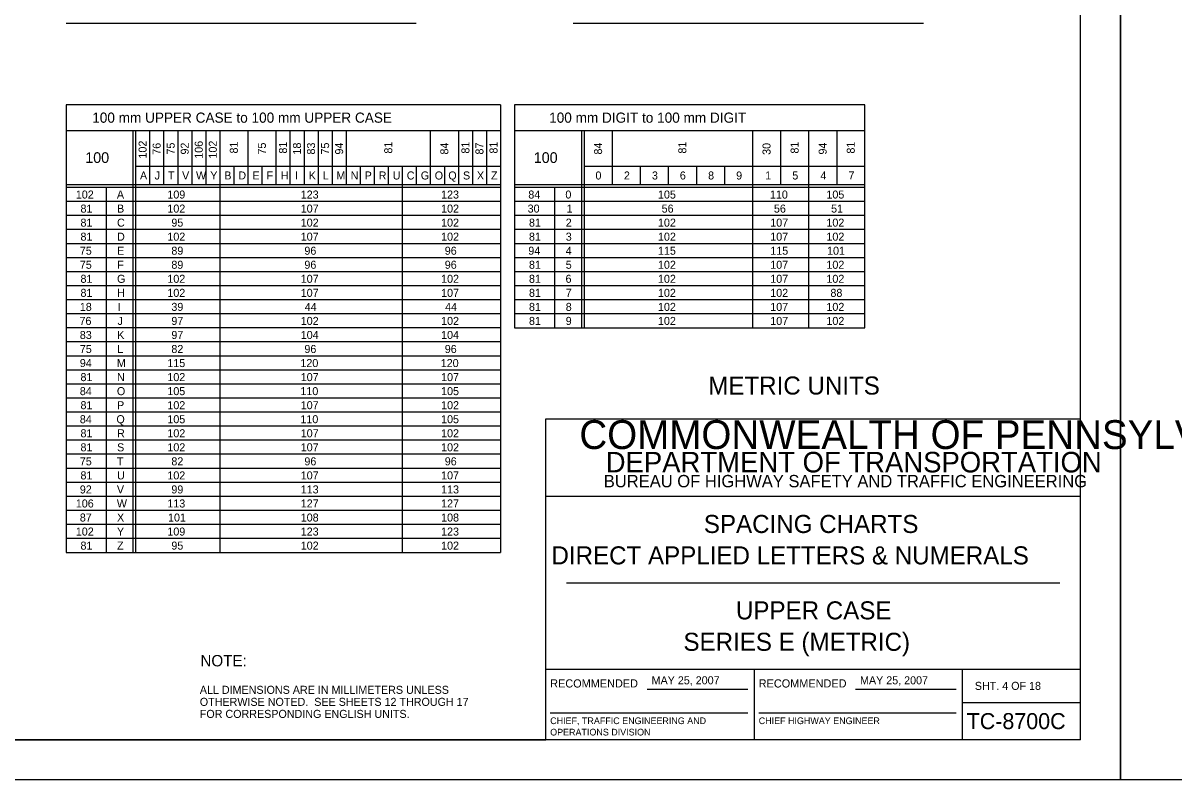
# Model space of a CAD drawing. Extents: x 637580 to 641849, y 297270 to 299646.
# Drawn here: x 638010.8 to 638441.3, y 297269.6 to 297552.6 of the extents above; entities that cross this region are included whole.
import ezdxf

# ---------------------------------------------------------------- set-up
doc = ezdxf.new("R2010")
doc.units = 0
for name, color, linetype in [('1', 7, 'Continuous'), ('2', 7, 'Continuous'), ('XCS-GRID-HVGL', 7, 'Continuous')]:
    doc.layers.add(name, color=color, linetype=linetype)

msp = doc.modelspace()

# ---------------------------------------------------------------- linework, layer by layer
at = {"layer": '1'}
for p, q in [((638406.31, 297284.63), (638406.31, 297848.63)), ((638206.31, 297284.63), (638206.31, 297404.63)), ((638206.31, 297404.63), (638406.31, 297404.63)), ((638406.31, 297375.63), (638206.31, 297375.63)), ((638214.06, 297343.31), (638398.56, 297343.31)), ((638206.31, 297311), (638406.31, 297311)), ((638284.31, 297311), (638284.31, 297284.63)), ((638362.19, 297284.63), (638362.19, 297311)), ((638244.24, 297303.57), (638281.87, 297303.57)), ((638322.24, 297303.57), (638359.87, 297303.57)), ((638362.19, 297298.63), (638406.31, 297298.63)), ((638207.99, 297294.68), (638281.87, 297294.68)), ((638285.99, 297294.68), (638359.87, 297294.68)), ((638406.31, 297284.63), (637620.31, 297284.63)), ((637620.31, 297284.63), (638206.31, 297284.63))]:
    msp.add_line(p, q, dxfattribs=at)
at = {"layer": '2'}
for p, q in [((638026.91, 297552.63), (638157.91, 297552.63)), ((638216.61, 297552.63), (638347.61, 297552.63)), ((638189.41, 297522), (638026.91, 297522)), ((638026.91, 297522), (638026.91, 297354.63)), ((638189.41, 297522), (638189.41, 297354.63)), ((638325.66, 297522), (638194.66, 297522)), ((638194.66, 297522), (638194.66, 297438.63)), ((638325.66, 297438.63), (638325.66, 297522)), ((638026.91, 297512.5), (638189.41, 297512.5)), ((638051.91, 297512.5), (638051.91, 297354.63)), ((638052.91, 297512.5), (638052.91, 297354.63)), ((638058.16, 297512.5), (638058.16, 297492.13)), ((638063.41, 297512.5), (638063.41, 297492.13)), ((638068.66, 297512.5), (638068.66, 297492.13)), ((638073.91, 297512.5), (638073.91, 297492.13)), ((638079.16, 297512.5), (638079.16, 297492.13)), ((638084.41, 297512.5), (638084.41, 297354.63)), ((638094.91, 297512.5), (638094.91, 297492.13)), ((638105.41, 297512.5), (638105.41, 297492.13)), ((638110.66, 297512.5), (638110.66, 297492.13)), ((638115.91, 297512.5), (638115.91, 297492.13)), ((638121.16, 297512.5), (638121.16, 297492.13)), ((638126.41, 297512.5), (638126.41, 297492.13)), ((638131.66, 297512.5), (638131.66, 297492.13)), ((638163.16, 297512.5), (638163.16, 297492.13)), ((638173.66, 297512.5), (638173.66, 297492.13)), ((638178.91, 297512.5), (638178.91, 297492.13)), ((638184.16, 297512.5), (638184.16, 297492.13)), ((638194.66, 297512.5), (638325.66, 297512.5)), ((638219.66, 297512.5), (638219.66, 297438.63)), ((638220.66, 297512.5), (638220.66, 297438.63)), ((638231.16, 297512.5), (638231.16, 297492.13)), ((638283.66, 297512.5), (638283.66, 297438.63)), ((638294.16, 297512.5), (638294.16, 297492.13)), ((638304.66, 297512.5), (638304.66, 297438.63)), ((638315.16, 297512.5), (638315.16, 297492.13)), ((638052.91, 297499.13), (638189.41, 297499.13)), ((638089.66, 297499.13), (638089.66, 297492.13)), ((638100.16, 297499.13), (638100.16, 297492.13)), ((638136.91, 297499.13), (638136.91, 297492.13)), ((638142.16, 297499.13), (638142.16, 297492.13)), ((638147.41, 297499.13), (638147.41, 297492.13)), ((638147.41, 297499.13), (638147.41, 297492.13)), ((638152.66, 297499.13), (638152.66, 297354.63)), ((638157.91, 297499.13), (638157.91, 297492.13)), ((638168.41, 297499.13), (638168.41, 297492.13)), ((638220.66, 297499.13), (638325.66, 297499.13)), ((638241.66, 297499.13), (638241.66, 297492.13)), ((638252.16, 297499.13), (638252.16, 297492.13)), ((638262.66, 297499.13), (638262.66, 297492.13)), ((638273.16, 297499.13), (638273.16, 297492.13)), ((638189.41, 297492.13), (638026.91, 297492.13)), ((638189.41, 297491.13), (638026.91, 297491.13)), ((638041.91, 297491.13), (638041.91, 297354.63)), ((638325.66, 297492.13), (638194.66, 297492.13)), ((638325.66, 297491.13), (638194.66, 297491.13)), ((638209.66, 297491.13), (638209.66, 297438.63)), ((638189.41, 297485.88), (638026.91, 297485.88)), ((638325.66, 297485.88), (638194.66, 297485.88)), ((638189.41, 297480.63), (638026.91, 297480.63)), ((638325.66, 297480.63), (638194.66, 297480.63)), ((638189.41, 297475.38), (638026.91, 297475.38)), ((638325.66, 297475.38), (638194.66, 297475.38)), ((638189.41, 297470.13), (638026.91, 297470.13)), ((638325.66, 297470.13), (638194.66, 297470.13)), ((638189.41, 297464.88), (638026.91, 297464.88)), ((638325.66, 297464.88), (638194.66, 297464.88)), ((638189.41, 297459.63), (638026.91, 297459.63)), ((638325.66, 297459.63), (638194.66, 297459.63)), ((638189.41, 297454.38), (638026.91, 297454.38)), ((638325.66, 297454.38), (638194.66, 297454.38)), ((638189.41, 297449.13), (638026.91, 297449.13)), ((638325.66, 297449.13), (638194.66, 297449.13)), ((638189.41, 297443.88), (638026.91, 297443.88)), ((638325.66, 297443.88), (638194.66, 297443.88)), ((638189.41, 297438.63), (638026.91, 297438.63)), ((638194.66, 297438.63), (638325.66, 297438.63)), ((638189.41, 297433.38), (638026.91, 297433.38)), ((638189.41, 297428.13), (638026.91, 297428.13)), ((638189.41, 297422.88), (638026.91, 297422.88)), ((638189.41, 297417.63), (638026.91, 297417.63)), ((638189.41, 297412.38), (638026.91, 297412.38)), ((638189.41, 297407.13), (638026.91, 297407.13)), ((638189.41, 297401.88), (638026.91, 297401.88)), ((638189.41, 297396.63), (638026.91, 297396.63)), ((638189.41, 297391.38), (638026.91, 297391.38)), ((638189.41, 297386.13), (638026.91, 297386.13)), ((638189.41, 297380.88), (638026.91, 297380.88)), ((638189.41, 297375.63), (638026.91, 297375.63)), ((638189.41, 297370.38), (638026.91, 297370.38)), ((638189.41, 297365.13), (638026.91, 297365.13)), ((638189.41, 297359.88), (638026.91, 297359.88)), ((638026.91, 297354.63), (638026.91, 297354.63)), ((638026.91, 297354.63), (638189.41, 297354.63))]:
    msp.add_line(p, q, dxfattribs=at)
at = {"layer": 'XCS-GRID-HVGL'}
for points in [[(637580.31, 297863.63), (638421.31, 297863.63), (638421.31, 297269.63), (637580.31, 297269.63)], [(638421.31, 297863.63), (639262.31, 297863.63), (639262.31, 297269.63), (638421.31, 297269.63)]]:
    msp.add_lwpolyline(points, close=True, dxfattribs=at)

# ---------------------------------------------------------------- texts
at = {"layer": '1'}
for s, height, p in [('COMMONWEALTH OF PENNSYLVANIA', 10.7828, (638218.9, 297393.36)), ('DEPARTMENT OF TRANSPORTATION', 7.6837, (638228.76, 297384.61)), ('BUREAU OF HIGHWAY SAFETY AND TRAFFIC ENGINEERING', 4.6253, (638228.04, 297379.04)), ('SPACING CHARTS', 6.75, (638265.47, 297361.97)), ('DIRECT APPLIED LETTERS & NUMERALS', 6.75, (638208.47, 297350.22)), ('UPPER CASE', 6.75, (638277.47, 297329.66)), ('SERIES E (METRIC)', 6.75, (638257.84, 297317.91)), ('RECOMMENDED', 3.048, (638207.99, 297304.2)), ('RECOMMENDED', 3.048, (638285.99, 297304.2)), ('SHT. 4 OF 18', 3, (638366.82, 297303.31)), ('TC-8700C', 6, (638363.77, 297288.63)), ('CHIEF, TRAFFIC ENGINEERING AND', 2.5, (638207.99, 297290.51)), ('CHIEF HIGHWAY ENGINEER', 2.5, (638285.99, 297290.51)), ('OPERATIONS DIVISION', 2.5, (638207.99, 297286.26))]:
    msp.add_text(s, height=height, dxfattribs=at).set_placement(p)
at = {"layer": '2'}
for s, height, p in [('100 mm UPPER CASE to 100 mm UPPER CASE', 3.8, (638036.7, 297515.35)), ('100 mm DIGIT to 100 mm DIGIT', 3.8, (638207.61, 297515.35)), ('100', 4, (638034.1, 297500.31)), ('100', 4, (638201.85, 297500.31)), ('A', 3, (638054.56, 297494.13)), ('J', 3, (638060.04, 297494.13)), ('T', 3, (638065.04, 297494.13)), ('V', 3, (638070.31, 297494.13)), ('W', 3, (638075.53, 297494.13)), ('Y', 3, (638080.84, 297494.13)), ('B', 3, (638086.1, 297494.13)), ('D', 3, (638091.35, 297494.13)), ('E', 3, (638096.62, 297494.13)), ('F', 3, (638101.92, 297494.13)), ('H', 3, (638107.19, 297494.13)), ('I', 3, (638112.6, 297494.13)), ('K', 3, (638117.69, 297494.13)), ('L', 3, (638122.94, 297494.13)), ('M', 3, (638128.03, 297494.13)), ('N', 3, (638133.35, 297494.13)), ('P', 3, (638138.6, 297494.13)), ('R', 3, (638143.85, 297494.13)), ('U', 3, (638149.09, 297494.13)), ('C', 3, (638154.35, 297494.13)), ('G', 3, (638159.6, 297494.13)), ('O', 3, (638164.81, 297494.13)), ('Q', 3, (638169.88, 297494.13)), ('S', 3, (638175.37, 297494.13)), ('X', 3, (638180.59, 297494.13)), ('Z', 3, (638185.85, 297494.13)), ('0', 3, (638224.93, 297494.13)), ('2', 3, (638235.56, 297494.13)), ('3', 3, (638246.06, 297494.13)), ('6', 3, (638256.48, 297494.13)), ('8', 3, (638267.06, 297494.13)), ('9', 3, (638277.55, 297494.13)), ('1', 3, (638288.4, 297494.13)), ('5', 3, (638298.56, 297494.13)), ('4', 3, (638309.06, 297494.13)), ('7', 3, (638319.56, 297494.13)), ('102', 3, (638030.56, 297487)), ('A', 3, (638045.93, 297487)), ('109', 3, (638064.8, 297487)), ('123', 3, (638114.69, 297487)), ('123', 3, (638167.19, 297487)), ('84', 3, (638199.81, 297487)), ('0', 3, (638213.68, 297487)), ('105', 3, (638248.31, 297487)), ('110', 3, (638290.18, 297487)), ('105', 3, (638311.31, 297487)), ('81', 3, (638032.31, 297481.75)), ('B', 3, (638045.98, 297481.75)), ('102', 3, (638064.8, 297481.75)), ('107', 3, (638114.69, 297481.75)), ('102', 3, (638167.19, 297481.75)), ('30', 3, (638199.56, 297481.75)), ('1', 3, (638214.15, 297481.75)), ('56', 3, (638249.69, 297481.75)), ('56', 3, (638291.68, 297481.75)), ('51', 3, (638313.06, 297481.75)), ('81', 3, (638032.31, 297476.5)), ('C', 3, (638045.98, 297476.5)), ('95', 3, (638066.3, 297476.5)), ('102', 3, (638114.69, 297476.5)), ('102', 3, (638167.19, 297476.5)), ('81', 3, (638200.06, 297476.5)), ('2', 3, (638213.81, 297476.5)), ('102', 3, (638248.31, 297476.5)), ('107', 3, (638290.31, 297476.5)), ('102', 3, (638311.31, 297476.5)), ('81', 3, (638032.31, 297471.25)), ('D', 3, (638045.98, 297471.25)), ('102', 3, (638064.8, 297471.25)), ('107', 3, (638114.69, 297471.25)), ('102', 3, (638167.19, 297471.25)), ('81', 3, (638200.06, 297471.25)), ('3', 3, (638213.81, 297471.25)), ('102', 3, (638248.31, 297471.25)), ('107', 3, (638290.31, 297471.25)), ('102', 3, (638311.31, 297471.25)), ('75', 3, (638032.06, 297466)), ('E', 3, (638045.99, 297466)), ('89', 3, (638066.3, 297466)), ('96', 3, (638116.06, 297466)), ('96', 3, (638168.56, 297466)), ('94', 3, (638199.81, 297466)), ('4', 3, (638213.81, 297466)), ('115', 3, (638248.31, 297466)), ('115', 3, (638290.31, 297466)), ('101', 3, (638311.56, 297466)), ('75', 3, (638032.06, 297460.75)), ('F', 3, (638046.05, 297460.75)), ('89', 3, (638066.3, 297460.75)), ('96', 3, (638116.06, 297460.75)), ('96', 3, (638168.56, 297460.75)), ('81', 3, (638200.06, 297460.75)), ('5', 3, (638213.81, 297460.75)), ('102', 3, (638248.31, 297460.75)), ('107', 3, (638290.31, 297460.75)), ('102', 3, (638311.31, 297460.75)), ('81', 3, (638032.31, 297455.5)), ('G', 3, (638045.98, 297455.5)), ('102', 3, (638064.8, 297455.5)), ('107', 3, (638114.69, 297455.5)), ('102', 3, (638167.19, 297455.5)), ('81', 3, (638200.06, 297455.5)), ('6', 3, (638213.73, 297455.5)), ('102', 3, (638248.31, 297455.5)), ('107', 3, (638290.31, 297455.5)), ('102', 3, (638311.31, 297455.5)), ('81', 3, (638032.31, 297450.25)), ('H', 3, (638046.06, 297450.25)), ('102', 3, (638064.8, 297450.25)), ('107', 3, (638114.69, 297450.25)), ('107', 3, (638167.19, 297450.25)), ('81', 3, (638200.06, 297450.25)), ('7', 3, (638213.81, 297450.25)), ('102', 3, (638248.31, 297450.25)), ('102', 3, (638290.31, 297450.25)), ('88', 3, (638312.81, 297450.25)), ('18', 3, (638032.06, 297445)), ('I', 3, (638046.23, 297445)), ('39', 3, (638066.3, 297445)), ('44', 3, (638116.19, 297445)), ('44', 3, (638168.69, 297445)), ('81', 3, (638200.06, 297445)), ('8', 3, (638213.81, 297445)), ('102', 3, (638248.31, 297445)), ('107', 3, (638290.31, 297445)), ('102', 3, (638311.31, 297445)), ('76', 3, (638031.94, 297439.75)), ('J', 3, (638046.17, 297439.75)), ('97', 3, (638066.3, 297439.75)), ('102', 3, (638114.69, 297439.75)), ('102', 3, (638167.19, 297439.75)), ('81', 3, (638200.06, 297439.75)), ('9', 3, (638213.8, 297439.75)), ('102', 3, (638248.31, 297439.75)), ('107', 3, (638290.31, 297439.75)), ('102', 3, (638311.31, 297439.75)), ('83', 3, (638032.06, 297434.5)), ('K', 3, (638046.06, 297434.5)), ('97', 3, (638066.3, 297434.5)), ('104', 3, (638114.69, 297434.5)), ('104', 3, (638167.19, 297434.5)), ('75', 3, (638032.06, 297429.25)), ('L', 3, (638046.06, 297429.25)), ('82', 3, (638066.3, 297429.25)), ('96', 3, (638116.06, 297429.25)), ('96', 3, (638168.56, 297429.25)), ('94', 3, (638032.06, 297424)), ('M', 3, (638045.91, 297424)), ('115', 3, (638064.8, 297424)), ('120', 3, (638114.56, 297424)), ('120', 3, (638167.06, 297424)), ('81', 3, (638032.31, 297418.75)), ('N', 3, (638045.98, 297418.75)), ('102', 3, (638064.8, 297418.75)), ('107', 3, (638114.69, 297418.75)), ('107', 3, (638167.19, 297418.75)), ('METRIC UNITS', 6.75, (638267.11, 297413.72)), ('84', 3, (638032.06, 297413.5)), ('O', 3, (638045.93, 297413.5)), ('105', 3, (638064.8, 297413.5)), ('110', 3, (638114.56, 297413.5)), ('105', 3, (638167.19, 297413.5)), ('81', 3, (638032.31, 297408.25)), ('P', 3, (638045.98, 297408.25)), ('102', 3, (638064.8, 297408.25)), ('107', 3, (638114.69, 297408.25)), ('102', 3, (638167.19, 297408.25)), ('84', 3, (638032.06, 297403)), ('Q', 3, (638045.75, 297403)), ('105', 3, (638064.8, 297403)), ('110', 3, (638114.56, 297403)), ('105', 3, (638167.19, 297403)), ('81', 3, (638032.31, 297397.75)), ('R', 3, (638045.98, 297397.75)), ('102', 3, (638064.8, 297397.75)), ('107', 3, (638114.69, 297397.75)), ('102', 3, (638167.19, 297397.75)), ('81', 3, (638032.31, 297392.5)), ('S', 3, (638045.99, 297392.5)), ('102', 3, (638064.8, 297392.5)), ('107', 3, (638114.69, 297392.5)), ('102', 3, (638167.19, 297392.5)), ('75', 3, (638032.06, 297387.25)), ('T', 3, (638045.92, 297387.25)), ('82', 3, (638066.3, 297387.25)), ('96', 3, (638116.06, 297387.25)), ('96', 3, (638168.56, 297387.25)), ('81', 3, (638032.31, 297382)), ('U', 3, (638045.97, 297382)), ('102', 3, (638064.8, 297382)), ('107', 3, (638114.69, 297382)), ('107', 3, (638167.19, 297382)), ('92', 3, (638032.06, 297376.75)), ('V', 3, (638045.93, 297376.75)), ('99', 3, (638066.3, 297376.75)), ('113', 3, (638114.69, 297376.75)), ('113', 3, (638167.19, 297376.75)), ('106', 3, (638030.56, 297371.5)), ('W', 3, (638045.91, 297371.5)), ('113', 3, (638064.8, 297371.5)), ('127', 3, (638114.69, 297371.5)), ('127', 3, (638167.19, 297371.5)), ('87', 3, (638032.06, 297366.25)), ('X', 3, (638045.97, 297366.25)), ('101', 3, (638065.05, 297366.25)), ('108', 3, (638114.69, 297366.25)), ('108', 3, (638167.19, 297366.25)), ('102', 3, (638030.56, 297361)), ('Y', 3, (638045.97, 297361)), ('109', 3, (638064.8, 297361)), ('123', 3, (638114.69, 297361)), ('123', 3, (638167.19, 297361)), ('81', 3, (638032.31, 297355.75)), ('Z', 3, (638045.98, 297355.75)), ('95', 3, (638066.3, 297355.75)), ('102', 3, (638114.69, 297355.75)), ('102', 3, (638167.19, 297355.75)), ('NOTE:', 4.25, (638077.16, 297312.1)), ('MAY 25, 2007', 3, (638245.93, 297305.39)), ('ALL DIMENSIONS ARE IN MILLIMETERS UNLESS', 3, (638076.94, 297301.83)), ('OTHERWISE NOTED.  SEE SHEETS 12 THROUGH 17', 3, (638076.94, 297297.33)), ('FOR CORRESPONDING ENGLISH UNITS.', 3, (638076.94, 297292.83))]:
    msp.add_text(s, height=height, dxfattribs=at).set_placement(p)
for s, rotation, p in [('102', 90, (638057.04, 297501.96)), ('76', 90, (638062.29, 297503.38)), ('75', 90, (638067.54, 297503.46)), ('92', 90, (638072.79, 297503.46)), ('106', 90, (638078.04, 297501.88)), ('102', 90, (638083.29, 297501.96)), ('81', 90, (638091.16, 297503.84)), ('75', 90, (638101.66, 297503.46)), ('81', 90, (638109.54, 297503.81)), ('18', 90, (638114.79, 297503.46)), ('83', 90, (638120.04, 297503.46)), ('75', 90, (638125.29, 297503.46)), ('94', 90, (638130.54, 297503.46)), ('81', 90, (638148.91, 297503.81)), ('84', 90, (638169.91, 297503.46)), ('81', 90, (638177.79, 297503.81)), ('87', 90, (638183.04, 297503.46)), ('81', 90, (638188.29, 297503.81)), ('84', 90, (638227.41, 297503.46)), ('81', 90, (638258.91, 297503.81)), ('30', 90, (638290.41, 297503.33)), ('81', 90, (638300.91, 297503.81)), ('94', 90, (638311.41, 297503.46)), ('81', 90, (638321.91, 297503.81)), ('MAY 25, 2007', 360, (638323.88, 297305.39))]:
    msp.add_text(s, height=3, rotation=rotation, dxfattribs=at).set_placement(p)

doc.saveas('drawing.dxf')
